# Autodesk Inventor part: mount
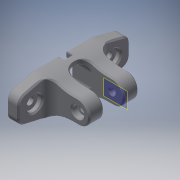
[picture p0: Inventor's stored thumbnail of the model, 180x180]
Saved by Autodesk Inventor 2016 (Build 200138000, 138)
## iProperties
Created: 2015-05
Part Number: mount
Material: Generic
Document SubType Name: Modeling
Designer: Brent
Density: 1 g/cm^3
Appearance: Default
Author: Brent
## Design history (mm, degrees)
sketch "Sketch1"
  geometry: L1 (-101.636, 6.429)-(-116.71, 6.429); L2 (-116.71, 6.429)-(-116.71, -6.429); L3 (-116.71, -6.429)-(-101.636, -6.429); C1 r 2.159 at (-101.636, 0) reference; C2 r 6.429 at (-101.636, 0); A1 r 6.429 centre (-101.636, 0) between (-101.636, 6.429) and (-101.636, -6.429) reference; 1 further point
  constraints: 6 end point, 2 perpendicular, 2 tangent, 1 centre point, 1 coincident, 1 horizontal
extrude "Extrusion1" new body sketch "Sketch1" distance "d0" = 7.9375; taper "d1" = 0 deg
workplane "Work Plane1"
sketch "Sketch2"
  geometry: L1 (101.636, -6.429)-(116.71, -6.429) reference; L2 (116.71, -6.429)-(116.71, 6.429) reference; L3 (116.71, 6.429)-(101.636, 6.429) reference; C1 r 2.159 at (101.636, 0) reference; A1 r 6.429 centre (101.636, 0) between (101.636, 6.429) and (101.636, -6.429) reference; 1 further point
extrude "Extrusion2" join sketch "Sketch2" distance "d2" = 7.9375; taper "d3" = 0 deg
sketch "Sketch3"
  geometry: L1 (4.401, 6.588)-(4.401, 12.303) reference; L2 (0, 0)-(0, 12.858) reference; L3 (0, 0)-(7.938, 0) reference; L4 (7.938, 12.858)-(7.938, 0) reference; L5 (0, 12.858)-(7.938, 12.858) reference; L6 (-10.668, 0)-(-10.668, 12.858) reference; L7 (-10.668, 12.858)-(-18.605, 12.858) reference; L8 (-18.605, 0)-(-18.605, 12.858) reference; L9 (-10.668, 0)-(-18.605, 0) reference; L10 (-35.375, 16.544)-(24.696, 16.544); L11 (24.696, 16.544)-(24.696, -3.368); L12 (24.696, -3.368)-(-35.375, -3.368); L13 (-35.375, -3.368)-(-35.375, 16.544); L14 (-35.375, 16.544)-(24.696, -3.368); L15 (24.696, 16.544)-(-35.375, -3.368); 2 further points
  constraints: 12 end point, 2 midpoint, 2 parallel, 1 horizontal, 1 perpendicular
extrude "Extrusion3" join sketch "Sketch3" distance "d4" = 6.35; taper "d5" = 0 deg
sketch "Sketch4"
  geometry: L1 (0, 12.858)-(-7.938, 12.858) reference; L2 (0, 0)-(0, 12.858) reference; L3 (0, 0)-(-7.938, 0) reference; L4 (-7.938, 12.858)-(-7.938, 0) reference; L5 (10.668, 0)-(18.605, 0) reference; L6 (10.668, 0)-(10.668, 12.858) reference; L7 (10.668, 12.858)-(18.605, 12.858) reference; L8 (18.605, 0)-(18.605, 12.858) reference; L9 (35.375, 16.544)-(-24.696, 16.544) reference; L10 (-24.696, 16.544)-(-24.696, -3.368) reference; L11 (-24.696, -3.368)-(35.375, -3.368) reference; L12 (35.375, -3.368)-(35.375, 16.544) reference; L13 (10.668, 0)-(18.605, 0) reference; L14 (0, 12.858)-(10.668, 12.858); L15 (10.668, 12.858)-(10.668, 0); L16 (10.668, 0)-(0, 0); L17 (0, 0)-(0, 12.858); 1 further point
  constraints: 8 end point, 2 parallel, 1 horizontal, 1 perpendicular
extrude "Extrusion4" cut sketch "Sketch4" distance "d6" = 9.525; taper "d7" = 0 deg
sketch "Sketch5"
  geometry: L1 (35.375, 16.544)-(-24.696, 16.544) reference; L2 (-24.696, 16.544)-(-24.696, -3.368) reference; L3 (-24.696, -3.368)-(35.375, -3.368) reference; L4 (35.375, -3.368)-(35.375, 16.544) reference; L5 (0, 12.858)-(10.668, 12.858) reference; L6 (10.668, 12.858)-(18.605, 12.858) reference; L7 (18.605, 0)-(18.605, 12.858) reference; L8 (10.668, 0)-(18.605, 0) reference; L9 (10.668, 0)-(0, 0) reference; L10 (0, 0)-(-7.938, 0) reference; L11 (-7.938, 12.858)-(-7.938, 0) reference; L12 (0, 12.858)-(-7.938, 12.858) reference; L13 (-24.696, 16.544)-(35.375, 16.544) reference; L14 (-10.088, 16.544)-(-24.696, 12.858); L15 (20.566, 16.544)-(35.375, 12.858); L16 (35.375, -3.368)-(-24.696, -3.368) reference; L17 (20.566, -3.368)-(35.375, 0); L18 (35.375, 16.544)-(35.375, -3.368) reference; L19 (-10.088, -3.368)-(-24.696, 0); 1 further point
  constraints: 8 end point, 8 point on line
extrude "Extrusion5" cut sketch "Sketch5" distance "d8" = 9.525; taper "d9" = 0 deg
fillet "Fillet1" dims "d10" = 4.7625
fillet "Fillet2" dims "d11" = 22.225
sketch "Sketch6"
  geometry: L1 (-7.938, -3.368)-(-7.937, 16.544) reference; L2 (20.566, 16.544)-(18.605, 16.544) reference; L3 (-10.088, 16.544)-(-21.099, 13.766) reference; L4 (-24.696, 9.148)-(-24.696, 3.789) reference; L5 (-21.003, -0.851)-(-10.088, -3.368) reference; L6 (-10.088, -3.368)-(-7.938, -3.368) reference; L7 (18.605, 16.544)-(18.606, -3.368) reference; L8 (-10.088, -3.368)-(-7.938, -3.368) reference; L9 (20.566, -3.368)-(31.669, -0.843) reference; L10 (35.375, 3.801)-(35.375, 9.136) reference; L11 (31.763, 13.757)-(20.566, 16.544) reference; L12 (20.566, 16.544)-(18.605, 16.544) reference; L13 (0, 0)-(0, -3.368) reference; L14 (0, -3.368)-(10.668, -3.368) reference; L15 (10.668, -3.368)-(10.668, 0) reference; L16 (10.668, 0)-(0, 0) reference; L17 (18.606, -3.368)-(20.566, -3.368) reference; L18 (-7.938, -3.368)-(-7.937, 16.544) reference; L19 (-7.937, 16.544)-(-10.088, 16.544) reference; L20 (-10.088, 16.544)-(-21.099, 13.766) reference; L21 (-24.696, 9.148)-(-24.696, 3.789) reference; L22 (-21.003, -0.851)-(-10.088, -3.368) reference; L23 (0, 16.544)-(0, 12.858) reference; L24 (0, 12.858)-(10.668, 12.858) reference; L25 (10.668, 12.858)-(10.668, 16.544) reference; L26 (10.668, 16.544)-(0, 16.544) reference; L27 (0, 0)-(0, -3.368) reference; L28 (0, -3.368)-(10.668, -3.368) reference; L29 (10.668, -3.368)-(10.668, 0) reference; L30 (10.668, 0)-(0, 0) reference; L31 (18.605, 16.544)-(18.606, -3.368) reference; L32 (18.606, -3.368)-(20.566, -3.368) reference; L33 (20.566, -3.368)-(31.669, -0.843) reference; L34 (35.375, 3.801)-(35.375, 9.136) reference; L35 (31.763, 13.757)-(20.566, 16.544) reference; L36 (-7.937, 16.544)-(-10.088, 16.544) reference; L37 (0, 16.544)-(0, 12.858) reference; L38 (0, 12.858)-(10.668, 12.858) reference; L39 (10.668, 12.858)-(10.668, 16.544) reference; L40 (10.668, 16.544)-(0, 16.544) reference; C1 r 1.905 at (-15.81, 6.468); C2 r 1.905 at (26.448, 6.468); A1 r 4.763 centre (-19.933, 9.148) between (-21.099, 13.766) and (-24.696, 9.148) reference; A2 r 4.763 centre (-19.933, 3.789) between (-24.696, 3.789) and (-21.003, -0.851) reference; A3 r 4.762 centre (30.613, 3.801) between (31.669, -0.843) and (35.375, 3.801) reference; A4 r 4.763 centre (30.613, 9.136) between (35.375, 9.136) and (31.763, 13.757) reference; A5 r 4.763 centre (-19.933, 9.148) between (-21.099, 13.766) and (-24.696, 9.148) reference; A6 r 4.763 centre (-19.933, 3.789) between (-24.696, 3.789) and (-21.003, -0.851) reference; A7 r 4.762 centre (30.613, 3.801) between (31.669, -0.843) and (35.375, 3.801) reference; A8 r 4.763 centre (30.613, 9.136) between (35.375, 9.136) and (31.763, 13.757) reference; 1 further point
  constraints: 2 centre point
  dimensions: "d12" = 3.81 diameter of C1
extrude "Extrusion6" cut sketch "Sketch6" distance "d13" = 9.525; taper "d14" = 0 deg
sketch "Sketch7"
  geometry: L1 (-7.938, -3.368)-(-7.937, 16.544) reference; L2 (20.566, 16.544)-(18.605, 16.544) reference; L3 (-10.088, 16.544)-(-21.099, 13.766) reference; L4 (-24.696, 9.148)-(-24.696, 3.789) reference; L5 (-21.003, -0.851)-(-10.088, -3.368) reference; L6 (-10.088, -3.368)-(-7.938, -3.368) reference; L7 (18.605, 16.544)-(18.606, -3.368) reference; L8 (-10.088, -3.368)-(-7.938, -3.368) reference; L9 (20.566, -3.368)-(31.669, -0.843) reference; L10 (35.375, 3.801)-(35.375, 9.136) reference; L11 (31.763, 13.757)-(20.566, 16.544) reference; L12 (20.566, 16.544)-(18.605, 16.544) reference; L13 (0, 0)-(0, -3.368) reference; L14 (0, -3.368)-(10.668, -3.368) reference; L15 (10.668, -3.368)-(10.668, 0) reference; L16 (10.668, 0)-(0, 0) reference; L17 (18.606, -3.368)-(20.566, -3.368) reference; L18 (-7.938, -3.368)-(-7.937, 16.544) reference; L19 (-7.937, 16.544)-(-10.088, 16.544) reference; L20 (-10.088, 16.544)-(-21.099, 13.766) reference; L21 (-24.696, 9.148)-(-24.696, 3.789) reference; L22 (-21.003, -0.851)-(-10.088, -3.368) reference; L23 (0, 16.544)-(0, 12.858) reference; L24 (0, 12.858)-(10.668, 12.858) reference; L25 (10.668, 12.858)-(10.668, 16.544) reference; L26 (10.668, 16.544)-(0, 16.544) reference; L27 (0, 0)-(0, -3.368) reference; L28 (0, -3.368)-(10.668, -3.368) reference; L29 (10.668, -3.368)-(10.668, 0) reference; L30 (10.668, 0)-(0, 0) reference; L31 (18.605, 16.544)-(18.606, -3.368) reference; L32 (18.606, -3.368)-(20.566, -3.368) reference; L33 (20.566, -3.368)-(31.669, -0.843) reference; L34 (35.375, 3.801)-(35.375, 9.136) reference; L35 (31.763, 13.757)-(20.566, 16.544) reference; L36 (-7.937, 16.544)-(-10.088, 16.544) reference; L37 (0, 16.544)-(0, 12.858) reference; L38 (0, 12.858)-(10.668, 12.858) reference; L39 (10.668, 12.858)-(10.668, 16.544) reference; L40 (10.668, 16.544)-(0, 16.544) reference; C1 r 1.905 at (-15.81, 6.468) reference; C2 r 1.905 at (26.448, 6.468) reference; C3 r 4.064 at (-15.81, 6.468); C4 r 4.064 at (26.448, 6.468); A1 r 4.763 centre (-19.933, 9.148) between (-21.099, 13.766) and (-24.696, 9.148) reference; A2 r 4.763 centre (-19.933, 3.789) between (-24.696, 3.789) and (-21.003, -0.851) reference; A3 r 4.762 centre (30.613, 3.801) between (31.669, -0.843) and (35.375, 3.801) reference; A4 r 4.763 centre (30.613, 9.136) between (35.375, 9.136) and (31.763, 13.757) reference; A5 r 4.763 centre (-19.933, 9.148) between (-21.099, 13.766) and (-24.696, 9.148) reference; A6 r 4.763 centre (-19.933, 3.789) between (-24.696, 3.789) and (-21.003, -0.851) reference; A7 r 4.762 centre (30.613, 3.801) between (31.669, -0.843) and (35.375, 3.801) reference; A8 r 4.763 centre (30.613, 9.136) between (35.375, 9.136) and (31.763, 13.757) reference; 1 further point
  constraints: 2 centre point, 2 coincident
  dimensions: "d15" = 8.128 diameter of C3; "d16" = 8.128 diameter of C4
extrude "Extrusion7" cut sketch "Sketch7" distance "d17" = 2.54; taper "d18" = 0 deg
fillet "Fillet3" dims "d19" = 4.7625
fillet "Fillet4" dims "d20" = 3.175
sketch "Sketch8"
  geometry: C1 r 3.81 at (0, 0) reference; C2 r 3.175 at (0, 0) reference; C3 r 2.159 at (-101.636, 0) reference; C4 r 3.175 at (-101.636, 0); 1 further point
  constraints: 1 centre point, 1 coincident
extrude "Extrusion8" cut sketch "Sketch8" distance "d21" = 3.048; taper "d22" = 0 deg
sketch "Sketch9"
  geometry: C1 r 1.524 at (101.636, 0) reference; C2 r 2.159 at (0, 0) reference; C3 r 1.524 at (0, 0); 1 further point
  constraints: 1 centre point, 1 coincident
extrude "Extrusion9" join sketch "Sketch9" distance "d23" = 4.8895; taper "d24" = 0 deg
sketch "Sketch10"
  geometry: C1 r 1.524 at (101.636, 0) reference; C2 r 2.159 at (101.636, 0) reference; 1 further point
extrude "Extrusion10" join sketch "Sketch10" distance "d25" = 7.9375; taper "d26" = 0 deg
sketch "Sketch11"
  geometry: L1 (101.636, 0)-(70.14, 0); L2 (98.462, 1.833)-(101.636, 3.666); L3 (101.636, 3.666)-(104.811, 1.833); L4 (104.811, 1.833)-(104.811, -1.833); L5 (104.811, -1.833)-(101.636, -3.666); L6 (101.636, -3.666)-(98.462, -1.833); L7 (98.462, -1.833)-(98.462, 1.833); C1 r 1.524 at (101.636, 0) reference; 4 further points
  constraints: 14 end point, 1 coincident, 1 horizontal, 1 horizontal alignment, 1 midpoint, 1 point on line, 14 other
  dimensions: "d27" = 31.496 distance of L1.start L1.end
extrude "Extrusion11" cut sketch "Sketch11" distance "d28" = 3.048; taper "d29" = 0 deg
chamfer "Chamfer1" distance "d30" = 0.508; stored, may be unused: second distance "d31" = 3.175, angle "d32" = 45 deg
chamfer "Chamfer3" distance "d36" = 0.762; stored, may be unused: second distance "d37" = 3.175, angle "d38" = 45 deg
chamfer "Chamfer4" distance "d39" = 0.762; stored, may be unused: second distance "d40" = 3.175, angle "d41" = 45 deg
sketch "Sketch12"
  geometry: L1 (24.696, 3.789)-(24.696, 9.148) reference; L2 (21.099, 13.766)-(10.088, 16.544) reference; L3 (10.088, 16.544)-(-20.566, 16.544) reference; L4 (-20.566, 16.544)-(-31.763, 13.757) reference; L5 (-35.375, 9.136)-(-35.375, 3.801) reference; L6 (-31.669, -0.843)-(-20.566, -3.368) reference; L7 (-20.566, -3.368)-(10.088, -3.368) reference; L8 (10.088, -3.368)-(21.003, -0.851) reference; L9 (-3.175, 0)-(-7.493, 0) reference; L10 (-10.668, 3.175)-(-10.668, 9.683) reference; L11 (-7.493, 12.858)-(-3.175, 12.858) reference; L12 (0, 9.683)-(0, 3.175) reference; L13 (-3.175, -5.438)-(-7.493, -5.438); L14 (-7.493, -5.438)-(-7.493, 18.296); L15 (-7.493, 18.296)-(-3.175, 18.296); L16 (-3.175, 18.296)-(-3.175, -5.438); L17 (-3.175, -5.438)-(-7.493, 18.296); L18 (-7.493, -5.438)-(-3.175, 18.296); C1 r 1.905 at (-26.448, 6.468) reference; C2 r 1.905 at (15.81, 6.468) reference; A1 r 4.763 centre (19.933, 3.789) between (21.003, -0.851) and (24.696, 3.789) reference; A2 r 4.763 centre (19.933, 9.148) between (24.696, 9.148) and (21.099, 13.766) reference; A3 r 4.763 centre (-30.613, 9.136) between (-31.763, 13.757) and (-35.375, 9.136) reference; A4 r 4.762 centre (-30.613, 3.801) between (-35.375, 3.801) and (-31.669, -0.843) reference; A5 r 3.175 centre (-7.493, 3.175) between (-10.668, 3.175) and (-7.493, 0) reference; A6 r 3.175 centre (-7.493, 9.683) between (-7.493, 12.858) and (-10.668, 9.683) reference; A7 r 3.175 centre (-3.175, 9.683) between (0, 9.683) and (-3.175, 12.858) reference; A8 r 3.175 centre (-3.175, 3.175) between (-3.175, 0) and (0, 3.175) reference; 2 further points
  constraints: 12 end point, 2 midpoint, 2 parallel, 1 horizontal, 1 perpendicular
extrude "Extrusion12" cut sketch "Sketch12" distance "d45" = 3.175; taper "d46" = 0 deg
chamfer "Chamfer6" distance "d47" = 0.762; stored, may be unused: second distance "d48" = 3.175, angle "d49" = 45 deg
fillet "Fillet5" dims "d50" = 1.27
fillet "Fillet6" dims "d51" = 29.845
fillet "Fillet7" dims "d52" = 12.7
body "Solid1"
node "Reference1"
node "Reference2"
node "Projected Loop1"
node "Reference3"
node "Projected Loop2"
node "Projected Loop3"
node "Projected Loop4"
node "Projected Loop5"
node "Projected Loop6"
node "Projected Loop7"
node "Projected Loop8"
node "Projected Loop9"
node "Reference4"
node "Reference5"
node "Reference6"
node "Projected Loop10"
